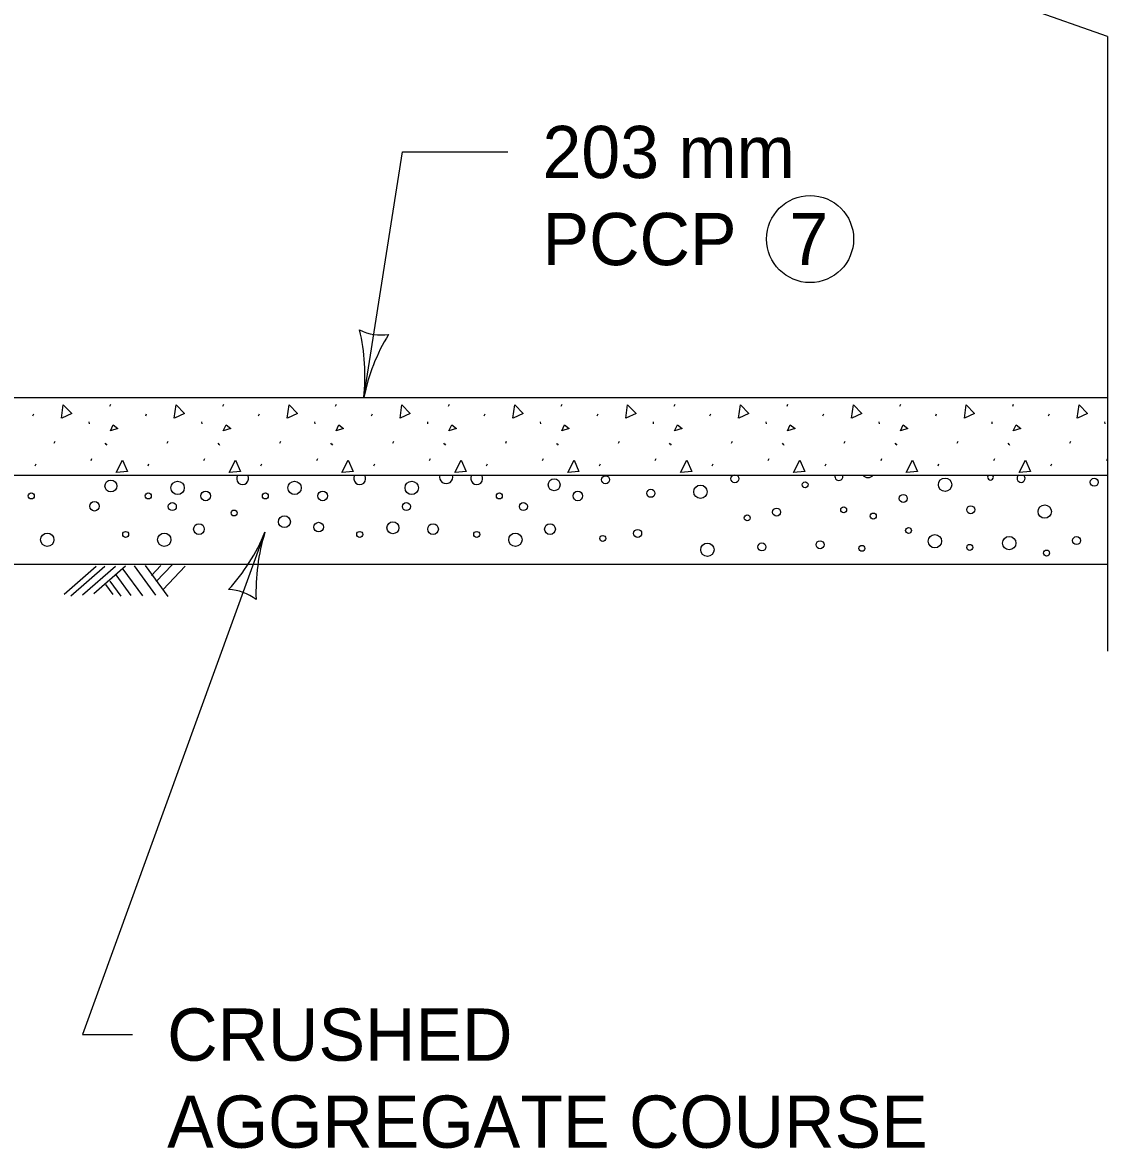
# Model space of a CAD drawing. Extents: x 49991.4 to 50021, y 49987.6 to 50011.4.
# Drawn here: x 50013.024 to 50014.27, y 49989.424 to 49990.718 of the extents above; entities that cross this region are included whole.
import ezdxf

# ---------------------------------------------------------------- set-up
doc = ezdxf.new("R2010")
doc.units = 0
for name, color, linetype in [('Level 1', 7, 'Continuous'), ('Level 2', 7, 'Continuous'), ('Level 3', 7, 'Continuous'), ('Level 6', 7, 'Continuous')]:
    doc.layers.add(name, color=color, linetype=linetype)

msp = doc.modelspace()

# ---------------------------------------------------------------- linework, layer by layer
at = {"layer": 'Level 1'}
for p, q in [((50012.3078, 49990.287), (50014.2703, 49990.287)), ((50012.3078, 49990.1979), (50014.2703, 49990.1979)), ((50012.1908, 49990.0955), (50014.2703, 49990.0955)), ((50013.1087, 49990.093), (50013.0717, 49990.0607)), ((50013.1185, 49990.093), (50013.0796, 49990.059)), ((50013.1308, 49990.0931), (50013.0927, 49990.06)), ((50013.1424, 49990.0934), (50013.106, 49990.0616)), ((50013.131, 49990.0834), (50013.1484, 49990.0596)), ((50013.1393, 49990.09), (50013.1618, 49990.0591)), ((50013.1522, 49990.0937), (50013.1768, 49990.0601)), ((50013.165, 49990.0939), (50013.191, 49990.0583)), ((50013.172, 49990.0825), (50013.1828, 49990.0939)), ((50013.1773, 49990.0756), (50013.1957, 49990.095)), ((50013.1855, 49990.0664), (50013.2109, 49990.0934)), ((50013.1191, 49990.0723), (50013.1275, 49990.0607)), ((50013.1244, 49990.0762), (50013.1369, 49990.059))]:
    msp.add_line(p, q, dxfattribs=at)
for centre, radius in [((50013.1254, 49990.1854), 0.00684), ((50013.2021, 49990.1832), 0.00766), ((50013.3365, 49990.1832), 0.00766), ((50013.471, 49990.1832), 0.00766), ((50013.6347, 49990.1868), 0.00684), ((50013.6937, 49990.1926), 0.0046), ((50013.8423, 49990.1938), 0.0046), ((50013.923, 49990.1868), 0.00341), ((50014.0837, 49990.1869), 0.00766), ((50014.2551, 49990.1898), 0.0046), ((50013.034, 49990.174), 0.00341), ((50013.1684, 49990.174), 0.00341), ((50013.2343, 49990.174), 0.00552), ((50013.3029, 49990.174), 0.00341), ((50013.3687, 49990.174), 0.00552), ((50013.5717, 49990.174), 0.00341), ((50013.6619, 49990.174), 0.00552), ((50013.7458, 49990.177), 0.0046), ((50013.8027, 49990.1788), 0.00766), ((50014.0357, 49990.1711), 0.0046), ((50013.1066, 49990.1622), 0.00552), ((50013.196, 49990.1618), 0.0046), ((50013.4649, 49990.1618), 0.0046), ((50013.5993, 49990.1618), 0.0046), ((50013.9673, 49990.1581), 0.00341), ((50014.1132, 49990.1581), 0.0046), ((50014.1982, 49990.156), 0.00766), ((50013.267, 49990.1544), 0.00341), ((50013.3248, 49990.1444), 0.00684), ((50013.8565, 49990.1488), 0.00341), ((50013.8902, 49990.1554), 0.0046), ((50014.0013, 49990.1509), 0.00341), ((50013.2266, 49990.1359), 0.00613), ((50013.3641, 49990.1382), 0.00552), ((50013.4494, 49990.1374), 0.00684), ((50013.4955, 49990.1359), 0.00613), ((50013.6299, 49990.1359), 0.00613), ((50013.7306, 49990.131), 0.0046), ((50014.0418, 49990.1343), 0.00341), ((50013.0524, 49990.1237), 0.00766), ((50013.1424, 49990.1298), 0.00341), ((50013.1868, 49990.1237), 0.00766), ((50013.4113, 49990.1298), 0.00341), ((50013.5457, 49990.1298), 0.00341), ((50013.5901, 49990.1237), 0.00766), ((50013.6905, 49990.1252), 0.00341), ((50013.9402, 49990.1179), 0.0046), ((50014.0721, 49990.122), 0.00766), ((50014.1575, 49990.1198), 0.00766), ((50014.2348, 49990.1228), 0.0046), ((50013.8107, 49990.1122), 0.00766), ((50013.8733, 49990.1154), 0.0046), ((50013.9882, 49990.1138), 0.00341), ((50014.1121, 49990.1149), 0.00341), ((50014.2004, 49990.1084), 0.00341)]:
    msp.add_circle(centre, radius, dxfattribs=at)
for centre, radius, start, end in [((50013.2768, 49990.1939), 0.00684, 143.5541, 36.4459), ((50013.4113, 49990.1939), 0.00684, 143.5541, 36.4459), ((50013.5106, 49990.1958), 0.00765, 163.8349, 16.1651), ((50013.5457, 49990.1939), 0.00684, 143.5541, 36.4459), ((50013.9618, 49990.1963), 0.0046, 159.2385, 20.7615), ((50013.9953, 49990.2028), 0.00766, 219.0724, 320.9276), ((50014.1359, 49990.1956), 0.00341, 135.9278, 44.0722), ((50014.1711, 49990.1942), 0.0046, 125.7802, 54.2198)]:
    msp.add_arc(centre, radius, start, end, dxfattribs=at)
at = {"layer": 'Level 2'}
msp.add_circle((50013.9287, 49990.4691), 0.05, dxfattribs=at)
at = {"layer": 'Level 3'}
for p, q in [((50013.4159, 49990.287), (50013.4603, 49990.5691)), ((50013.4603, 49990.5691), (50013.5813, 49990.5691)), ((50013.1242, 49990.2771), (50013.1253, 49990.2796)), ((50013.2539, 49990.2771), (50013.255, 49990.2796)), ((50013.3835, 49990.2771), (50013.3846, 49990.2796)), ((50013.5132, 49990.2771), (50013.5143, 49990.2796)), ((50013.6428, 49990.2771), (50013.6439, 49990.2796)), ((50013.7725, 49990.2771), (50013.7736, 49990.2796)), ((50013.9022, 49990.2771), (50013.9032, 49990.2796)), ((50014.0318, 49990.2771), (50014.0329, 49990.2796)), ((50014.1615, 49990.2771), (50014.1625, 49990.2796)), ((50013.0357, 49990.266), (50013.0368, 49990.2685)), ((50013.1654, 49990.266), (50013.1664, 49990.2685)), ((50013.295, 49990.266), (50013.2961, 49990.2685)), ((50013.4247, 49990.266), (50013.4258, 49990.2685)), ((50013.5543, 49990.266), (50013.5554, 49990.2685)), ((50013.684, 49990.266), (50013.6851, 49990.2685)), ((50013.8136, 49990.266), (50013.8147, 49990.2685)), ((50013.9433, 49990.266), (50013.9444, 49990.2685)), ((50014.073, 49990.266), (50014.074, 49990.2685)), ((50014.2026, 49990.266), (50014.2037, 49990.2685)), ((50013.1001, 49990.2592), (50013.1003, 49990.2568)), ((50013.2297, 49990.2592), (50013.23, 49990.2568)), ((50013.3594, 49990.2592), (50013.3596, 49990.2568)), ((50013.489, 49990.2592), (50013.4893, 49990.2568)), ((50013.6187, 49990.2592), (50013.619, 49990.2568)), ((50013.7483, 49990.2592), (50013.7486, 49990.2568)), ((50013.878, 49990.2592), (50013.8783, 49990.2568)), ((50014.0076, 49990.2592), (50014.0079, 49990.2568)), ((50014.1373, 49990.2592), (50014.1376, 49990.2568)), ((50014.267, 49990.2592), (50014.2672, 49990.2568)), ((50013.0603, 49990.2346), (50013.0614, 49990.2371)), ((50013.1185, 49990.2346), (50013.1196, 49990.233)), ((50013.1196, 49990.234), (50013.1207, 49990.2324)), ((50013.19, 49990.2346), (50013.1911, 49990.2371)), ((50013.2482, 49990.2346), (50013.2493, 49990.233)), ((50013.2493, 49990.234), (50013.2504, 49990.2324)), ((50013.3197, 49990.2346), (50013.3207, 49990.2371)), ((50013.3778, 49990.2346), (50013.3789, 49990.233)), ((50013.3789, 49990.234), (50013.38, 49990.2324)), ((50013.4493, 49990.2346), (50013.4504, 49990.2371)), ((50013.5075, 49990.2346), (50013.5086, 49990.233)), ((50013.5086, 49990.234), (50013.5097, 49990.2324)), ((50013.579, 49990.2346), (50013.58, 49990.2371)), ((50013.6372, 49990.2346), (50013.6382, 49990.233)), ((50013.6382, 49990.234), (50013.6393, 49990.2324)), ((50013.7086, 49990.2346), (50013.7097, 49990.2371)), ((50013.7668, 49990.2346), (50013.7679, 49990.233)), ((50013.7679, 49990.234), (50013.769, 49990.2324)), ((50013.8383, 49990.2346), (50013.8394, 49990.2371)), ((50013.8965, 49990.2346), (50013.8976, 49990.233)), ((50013.8976, 49990.234), (50013.8986, 49990.2324)), ((50013.9679, 49990.2346), (50013.969, 49990.2371)), ((50014.0261, 49990.2346), (50014.0272, 49990.233)), ((50014.0272, 49990.234), (50014.0283, 49990.2324)), ((50014.0976, 49990.2346), (50014.0987, 49990.2371)), ((50014.1558, 49990.2346), (50014.1569, 49990.233)), ((50014.1569, 49990.234), (50014.1579, 49990.2324)), ((50014.2272, 49990.2346), (50014.2283, 49990.2371)), ((50013.1026, 49990.2146), (50013.1036, 49990.217)), ((50013.2322, 49990.2146), (50013.2333, 49990.217)), ((50013.3619, 49990.2146), (50013.363, 49990.217)), ((50013.4915, 49990.2146), (50013.4926, 49990.217)), ((50013.6212, 49990.2146), (50013.6223, 49990.217)), ((50013.7508, 49990.2146), (50013.7519, 49990.217)), ((50013.8805, 49990.2146), (50013.8816, 49990.217)), ((50014.0102, 49990.2146), (50014.0112, 49990.217)), ((50014.1398, 49990.2146), (50014.1409, 49990.217)), ((50014.2695, 49990.2146), (50014.2703, 49990.2166)), ((50013.0384, 49990.2084), (50013.0395, 49990.2108)), ((50013.1681, 49990.2084), (50013.1692, 49990.2108)), ((50013.2977, 49990.2084), (50013.2988, 49990.2108)), ((50013.4274, 49990.2084), (50013.4285, 49990.2108)), ((50013.557, 49990.2084), (50013.5581, 49990.2108)), ((50013.6867, 49990.2084), (50013.6878, 49990.2108)), ((50013.8163, 49990.2084), (50013.8174, 49990.2108)), ((50013.946, 49990.2084), (50013.9471, 49990.2108)), ((50014.0757, 49990.2084), (50014.0767, 49990.2108)), ((50014.2053, 49990.2084), (50014.2064, 49990.2108)), ((50013.3024, 49990.1322), (50013.0927, 49989.5552)), ((50013.0927, 49989.5552), (50013.1501, 49989.5552))]:
    msp.add_line(p, q, dxfattribs=at)
for points in [[(50013.0686, 49990.2632), (50013.0708, 49990.2787), (50013.0805, 49990.2687), (50013.0689, 49990.2633)], [(50013.1983, 49990.2632), (50013.2004, 49990.2787), (50013.2101, 49990.2687), (50013.1985, 49990.2633)], [(50013.328, 49990.2632), (50013.3301, 49990.2787), (50013.3398, 49990.2687), (50013.3282, 49990.2633)], [(50013.4576, 49990.2632), (50013.4598, 49990.2787), (50013.4694, 49990.2687), (50013.4579, 49990.2633)], [(50013.5873, 49990.2632), (50013.5894, 49990.2787), (50013.5991, 49990.2687), (50013.5875, 49990.2633)], [(50013.7169, 49990.2632), (50013.7191, 49990.2787), (50013.7288, 49990.2687), (50013.7172, 49990.2633)], [(50013.8466, 49990.2632), (50013.8487, 49990.2787), (50013.8584, 49990.2687), (50013.8468, 49990.2633)], [(50013.9762, 49990.2632), (50013.9784, 49990.2787), (50013.9881, 49990.2687), (50013.9765, 49990.2633)], [(50014.1059, 49990.2632), (50014.108, 49990.2787), (50014.1177, 49990.2687), (50014.1061, 49990.2633)], [(50014.2355, 49990.2632), (50014.2377, 49990.2787), (50014.2474, 49990.2687), (50014.2358, 49990.2633)], [(50013.1248, 49990.2487), (50013.128, 49990.2555), (50013.1334, 49990.2514), (50013.1248, 49990.2487)], [(50013.2544, 49990.2487), (50013.2577, 49990.2555), (50013.2631, 49990.2514), (50013.2544, 49990.2487)], [(50013.3841, 49990.2487), (50013.3873, 49990.2555), (50013.3927, 49990.2514), (50013.3841, 49990.2487)], [(50013.5137, 49990.2487), (50013.517, 49990.2555), (50013.5224, 49990.2514), (50013.5137, 49990.2487)], [(50013.6434, 49990.2487), (50013.6466, 49990.2555), (50013.652, 49990.2514), (50013.6434, 49990.2487)], [(50013.773, 49990.2487), (50013.7763, 49990.2555), (50013.7817, 49990.2514), (50013.773, 49990.2487)], [(50013.9027, 49990.2487), (50013.9059, 49990.2555), (50013.9114, 49990.2514), (50013.9027, 49990.2487)], [(50014.0324, 49990.2487), (50014.0356, 49990.2555), (50014.041, 49990.2514), (50014.0324, 49990.2487)], [(50014.162, 49990.2487), (50014.1653, 49990.2555), (50014.1707, 49990.2514), (50014.162, 49990.2487)], [(50013.1315, 49990.2011), (50013.1388, 49990.2149), (50013.1445, 49990.2021), (50013.1318, 49990.2011)], [(50013.2612, 49990.2011), (50013.2685, 49990.2149), (50013.2742, 49990.2021), (50013.2615, 49990.2011)], [(50013.3908, 49990.2011), (50013.3982, 49990.2149), (50013.4038, 49990.2021), (50013.3911, 49990.2011)], [(50013.5205, 49990.2011), (50013.5278, 49990.2149), (50013.5335, 49990.2021), (50013.5208, 49990.2011)], [(50013.6502, 49990.2011), (50013.6575, 49990.2149), (50013.6631, 49990.2021), (50013.6504, 49990.2011)], [(50013.7798, 49990.2011), (50013.7871, 49990.2149), (50013.7928, 49990.2021), (50013.7801, 49990.2011)], [(50013.9095, 49990.2011), (50013.9168, 49990.2149), (50013.9225, 49990.2021), (50013.9097, 49990.2011)], [(50014.0391, 49990.2011), (50014.0464, 49990.2149), (50014.0521, 49990.2021), (50014.0394, 49990.2011)], [(50014.1688, 49990.2011), (50014.1761, 49990.2149), (50014.1818, 49990.2021), (50014.169, 49990.2011)]]:
    msp.add_lwpolyline(points, dxfattribs=at)
for centre, radius, start, end in [((50013.4359, 49990.4137), 0.0548, 243.2047, 278.927), ((50013.1843, 49990.3118), 0.233, 353.8932, 13.143), ((50013.634, 49990.2435), 0.2223, 148.5219, 168.7054), ((50013.0968, 49990.2167), 0.2223, 317.4833, 337.6668), ((50013.5251, 49990.0635), 0.233, 162.8546, 182.1044), ((50013.2587, 49990.0117), 0.0548, 52.1661, 87.8884)]:
    msp.add_arc(centre, radius, start, end, dxfattribs=at)
at = {"layer": 'Level 6'}
for q in [(50014.1789, 49990.734), (50014.2703, 49989.9955)]:
    msp.add_line((50014.2703, 49990.7016), q, dxfattribs=at)

# ---------------------------------------------------------------- texts
at = {"layer": 'Level 2'}
for s, p in [('203 mm', (50013.6213, 49990.5391)), ('PCCP', (50013.6213, 49990.4391)), ('7', (50013.9049, 49990.4391)), ('CRUSHED', (50013.1901, 49989.5252)), ('AGGREGATE COURSE', (50013.1901, 49989.4252))]:
    msp.add_text(s, height=0.06, dxfattribs=at).set_placement(p)

doc.saveas('drawing.dxf')
